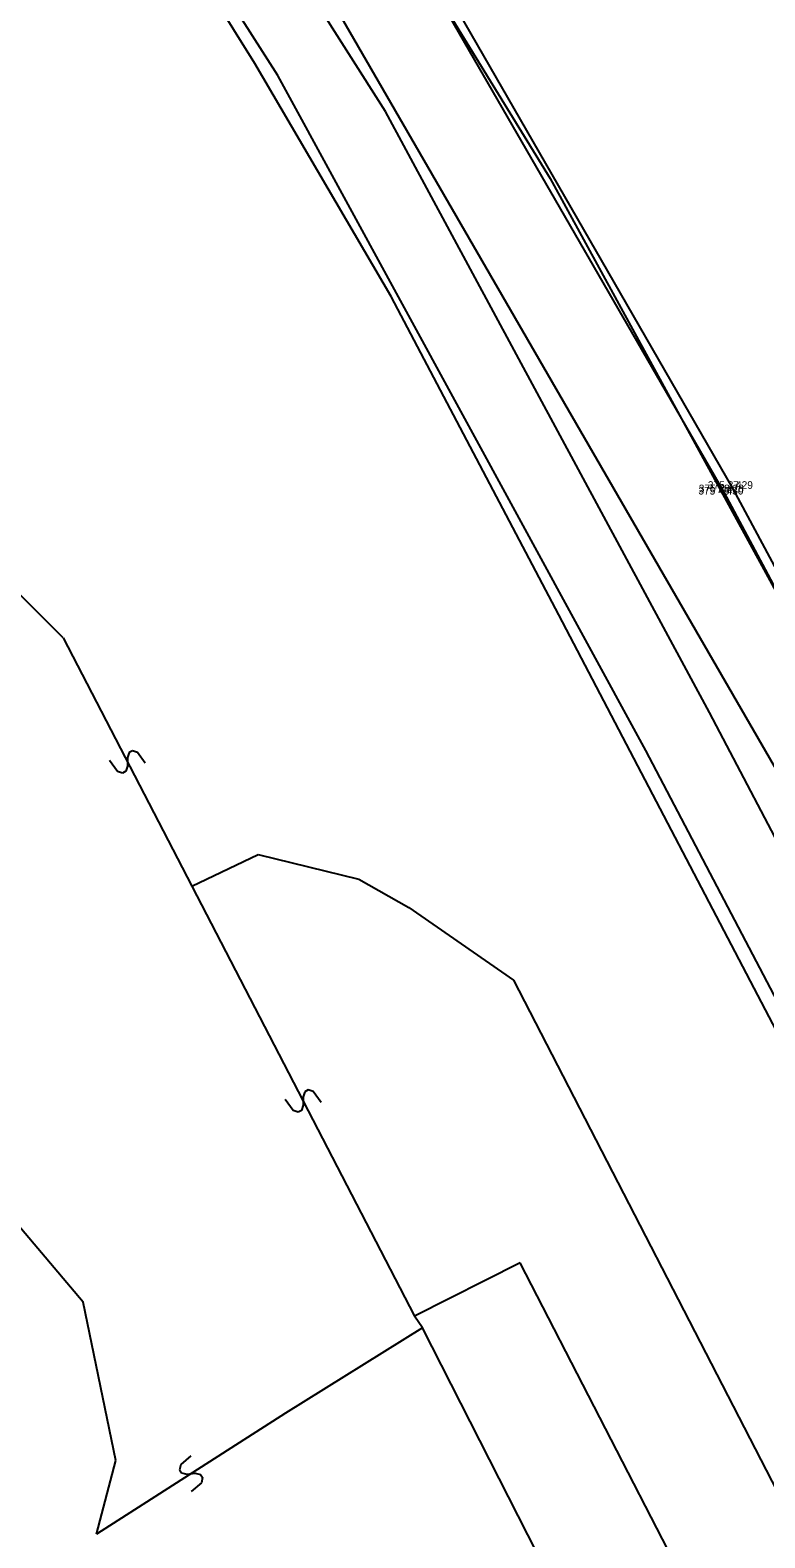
# Model space of a CAD drawing. Extents: x -601196 to -600262, y -1082523 to -1081922.
# Drawn here: x -600594.04 to -600574.7, y -1082148.5 to -1082108.8 of the extents above; entities that cross this region are included whole.
import ezdxf

# ---------------------------------------------------------------- set-up
doc = ezdxf.new("R2010")
doc.units = 0
for name, color, linetype in [('Vrstva 1', 7, 'Continuous'), ('Vrstva 10', 7, 'Continuous'), ('Vrstva 11', 7, 'Continuous'), ('Vrstva 2', 7, 'Continuous'), ('Vrstva 20', 7, 'Continuous'), ('Vrstva 3', 7, 'Continuous'), ('Vrstva 47', 7, 'Continuous')]:
    doc.layers.add(name, color=color, linetype=linetype)

msp = doc.modelspace()

# ---------------------------------------------------------------- linework, layer by layer
at = {"layer": 'Vrstva 1'}
for p, q in [((-600575.78, -1082121.03), (-600575.78, -1082121.03)), ((-600575.77, -1082120.97), (-600575.77, -1082120.97)), ((-600575.53, -1082120.88), (-600575.53, -1082120.88))]:
    msp.add_line(p, q, dxfattribs=at)
at = {"layer": 'Vrstva 10'}
for p, q in [((-600575.77, -1082120.97), (-600582.99, -1082108.45)), ((-600567.11, -1082137.17), (-600575.77, -1082120.97))]:
    msp.add_line(p, q, dxfattribs=at)
at = {"layer": 'Vrstva 11'}
for p, q in [((-600575.53, -1082120.88), (-600582.76, -1082108.32)), ((-600566.89, -1082137.01), (-600575.53, -1082120.88))]:
    msp.add_line(p, q, dxfattribs=at)
at = {"layer": 'Vrstva 20'}
for p, q in [((-600575.79, -1082121.03), (-600575.77, -1082121.03)), ((-600575.78, -1082121.015), (-600575.78, -1082121.03)), ((-600575.78, -1082121.045), (-600575.78, -1082121.03))]:
    msp.add_line(p, q, dxfattribs=at)
at = {"layer": 'Vrstva 47'}
for p, q in [((-600584.68, -1082110.95), (-600593.44, -1082097.12)), ((-600587.52, -1082110), (-600594.59, -1082098.83)), ((-600588.12, -1082109.68), (-600592.58, -1082102.53)), ((-600573.39, -1082130.02), (-600587.67, -1082105.3)), ((-600584.68, -1082105.64), (-600580.35, -1082112.71)), ((-600584.53, -1082115.82), (-600588.12, -1082109.68)), ((-600577.83, -1082127.77), (-600587.52, -1082110)), ((-600576.15, -1082126.77), (-600584.68, -1082110.95)), ((-600580.35, -1082112.71), (-600573.4, -1082125.43)), ((-600580.12, -1082124.2), (-600584.53, -1082115.82)), ((-600593.17, -1082124.8), (-600594.97, -1082123)), ((-600571.36, -1082140.95), (-600580.12, -1082124.2)), ((-600593.17, -1082124.8), (-600589.78, -1082131.34)), ((-600565.94, -1082146.26), (-600576.15, -1082126.77)), ((-600591.433, -1082127.823), (-600591.476, -1082127.958)), ((-600591.345, -1082127.777), (-600591.433, -1082127.823)), ((-600591.21, -1082127.82), (-600591.345, -1082127.777)), ((-600591.004, -1082128.107), (-600591.21, -1082127.82)), ((-600567.57, -1082147.35), (-600577.83, -1082127.77)), ((-600591.739, -1082128.319), (-600591.945, -1082128.032)), ((-600591.473, -1082128.181), (-600591.516, -1082128.316)), ((-600591.476, -1082127.958), (-600591.473, -1082128.181)), ((-600591.604, -1082128.362), (-600591.739, -1082128.319)), ((-600591.516, -1082128.316), (-600591.604, -1082128.362)), ((-600589.78, -1082131.34), (-600588.03, -1082130.51)), ((-600588.03, -1082130.51), (-600585.38, -1082131.16)), ((-600589.78, -1082131.34), (-600583.92, -1082142.66)), ((-600585.38, -1082131.16), (-600584.07, -1082131.9)), ((-600584.07, -1082131.9), (-600581.31, -1082133.82)), ((-600581.31, -1082133.82), (-600565.74, -1082164.04)), ((-600587.114, -1082137.249), (-600587.32, -1082136.961)), ((-600586.808, -1082136.753), (-600586.851, -1082136.888)), ((-600586.851, -1082136.888), (-600586.848, -1082137.111)), ((-600586.719, -1082136.707), (-600586.808, -1082136.753)), ((-600586.585, -1082136.75), (-600586.719, -1082136.707)), ((-600586.379, -1082137.038), (-600586.585, -1082136.75)), ((-600586.98, -1082137.292), (-600587.114, -1082137.249)), ((-600586.891, -1082137.246), (-600586.98, -1082137.292)), ((-600586.848, -1082137.111), (-600586.891, -1082137.246)), ((-600592.64, -1082142.29), (-600595.76, -1082138.61)), ((-600581.14, -1082141.26), (-600583.92, -1082142.66)), ((-600568.53, -1082165.69), (-600581.14, -1082141.26)), ((-600591.78, -1082146.46), (-600592.64, -1082142.29)), ((-600583.71, -1082142.97), (-600583.92, -1082142.66)), ((-600583.71, -1082142.97), (-600587.31, -1082145.22)), ((-600575.98, -1082158.15), (-600583.71, -1082142.97)), ((-600587.31, -1082145.22), (-600592.29, -1082148.4)), ((-600592.29, -1082148.4), (-600591.78, -1082146.46)), ((-600589.804, -1082146.338), (-600590.072, -1082146.568)), ((-600590.072, -1082146.568), (-600590.103, -1082146.706)), ((-600590.103, -1082146.706), (-600590.049, -1082146.791)), ((-600590.049, -1082146.791), (-600589.911, -1082146.821)), ((-600589.911, -1082146.821), (-600589.688, -1082146.798)), ((-600589.688, -1082146.798), (-600589.55, -1082146.828)), ((-600589.55, -1082146.828), (-600589.496, -1082146.913)), ((-600589.527, -1082147.051), (-600589.795, -1082147.281)), ((-600589.496, -1082146.913), (-600589.527, -1082147.051))]:
    msp.add_line(p, q, dxfattribs=at)

# ---------------------------------------------------------------- texts
at = {"layer": 'Vrstva 2'}
for s, p in [(' 429', (-600575.53, -1082120.88)), (' 430', (-600575.78, -1082121.03)), (' 428', (-600575.77, -1082120.97))]:
    msp.add_text(s, height=0.2, dxfattribs=at).set_placement(p)
at = {"layer": 'Vrstva 3'}
for s, p in [('375 37 ', (-600576.196, -1082120.88)), ('375 45 ', (-600576.446, -1082121.03)), ('375 38 ', (-600576.436, -1082120.97))]:
    msp.add_text(s, height=0.2, dxfattribs=at).set_placement(p)

doc.saveas('drawing.dxf')
